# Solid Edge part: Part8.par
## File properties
Author: TIET
Template: Iso Metric Part.par
Last saved by: TIET
Revision: 2
Application: Solid Edge
Accuracy: 0.990
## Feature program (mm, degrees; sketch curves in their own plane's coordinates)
sketch for "unnamed Protrusion 1" plane through (0, 0, 0) normal (0, 1, 0) x-axis (1, 0, 0)
  circle centre (0, 0) radius 87.1438
extrude "unnamed Protrusion 1" add finite 20.9072 along -normal
sketch for "ExtrudedProtrusion_2" #1 plane through (0, -20.9072, 0) normal (0, -1, 0) x-axis (1, 0, 0)
  circle centre (0, 0) radius 29.2182
sketch for "ExtrudedProtrusion_2" #2 plane through (0, -20.9072, 0) normal (0, -1, 0) x-axis (1, 0, 0)
  circle centre (0, 0) radius 42.9092
extrude "ExtrudedProtrusion_2" add finite 29.1638 along +normal
sketch for "ExtrudedCutout_1" plane through (0, -20.9072, 0) normal (0, -1, 0) x-axis (1, 0, 0)
  circle centre (0, 63.4817) radius 6.8014
extrude "ExtrudedCutout_1" cut finite 88.7737 along -normal
pattern "unnamed Pattern 1" of "ExtrudedCutout_1"
extrude "unnamed Cutout 1" cut finite 88.7737
extrude "unnamed Cutout 2" cut finite 88.7737
extrude "unnamed Cutout 3" cut finite 88.7737
extrude "unnamed Cutout 4" cut finite 88.7737
extrude "unnamed Cutout 5" cut finite 88.7737
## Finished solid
Body 1: solid body, 13 faces, 18 edges, 0 vertices.
  Faces by surface: cylinder 9, plane 4
  Edges by curve: circle 18
Bounding box of the edges (mm): 174.288 x 50.071 x 174.288, from (-87.1438, -50.071, -87.1438) to (87.1438, 0, 87.1438).
Cylindrical faces by radius (mm): R6.8014 x6, R29.2182 x1, R42.9092 x1, R87.1438 x1
Planar faces by outward normal: +y 1, -y 3
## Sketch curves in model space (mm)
circle centre (0, -20.9072, 63.4817) radius 6.8014
circle centre (0, -20.9072, 0) radius 42.9092
circle centre (0, -20.9072, 0) radius 29.2182
circle centre (0, 0, 0) radius 87.1438
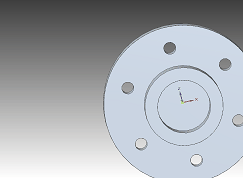
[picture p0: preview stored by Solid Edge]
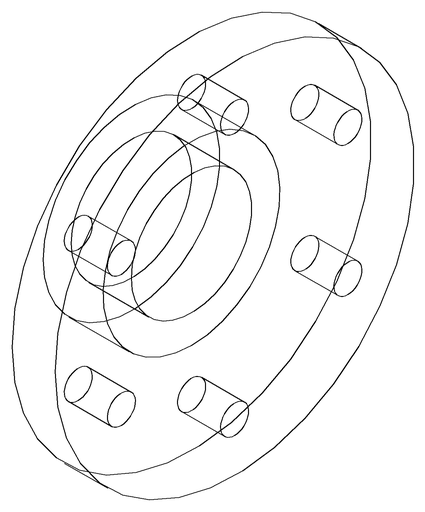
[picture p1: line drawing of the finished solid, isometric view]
